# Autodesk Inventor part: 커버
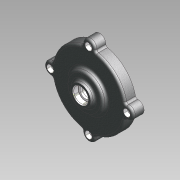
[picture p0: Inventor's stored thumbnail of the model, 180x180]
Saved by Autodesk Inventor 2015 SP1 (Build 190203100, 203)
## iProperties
Company: 한국ATC센터
Created: 2014-07
Part Number: 커버
Document SubType Name: 모델링
Designer: KYOUNG IL JANG
Material: 알루미늄 6061
Mass: 195.931 g
Surface Area: 278.607 cm^2
Volume: 72.5671 cm^3
Density: 2.7 g/cm^3
Appearance: 알루미늄 캐스트
변환 표준: STEP AP214IS
파일 이름: C:\Users\SeoGD\Desktop\?쒗뿕\而ㅻ쾭-1.stp
전처리기: Build: 253, Release: 2010 SP1 - Date: Wed 07/29/2009
전송 단위: 밀리미터
불확실성: 0.01
Author: KYOUNG IL JANG
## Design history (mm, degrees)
sketch "스케치1"
  geometry: L1 (0, 0)-(0, 26); L2 (50, 0)-(50, 15); L3 (50, 15)-(25, 15); L4 (25, 15)-(25, 21); L5 (25, 21)-(15, 21); L6 (15, 21)-(13.66, 26); L7 (13.66, 26)-(10, 26); L8 (50, 0)-(45, 0); L9 (45, 0)-(45, 10); L10 (45, 10)-(14.5, 10); L11 (14.5, 10)-(13.266, 3); L12 (13.266, 3)-(11, 3); L13 (11, 3)-(11, 16); L14 (11, 16)-(7.5, 16); L15 (7.5, 16)-(7.5, 19); L16 (7.5, 19)-(10, 19); L17 (10, 19)-(10, 26)
  constraints: 34 end point, 10 parallel, 2 perpendicular, 2 point on line, 1 vertical
  dimensions: "d11" = 100 diameter of L2 L1; "d12" = 22 diameter of L13 L1; "d13" = 90 diameter of L9 L1; "d14" = 15 distance between parallel lines of L3 L8; "d15" = 10 distance between parallel lines of L8 L10; "d16" = 29 diameter of L10.end L1; "d17" = 100 deg angle of L11 L10; "d18" = 7 distance between parallel lines of L12 L10; "d19" = 13 distance between parallel lines of L14 L12; "d20" = 3 distance between parallel lines of L16 L14; "d21" = 15 diameter of L15 L1; "d22" = 20 diameter of L17 L1; "d23" = 30 diameter of L5.end L1; "d24" = 6 distance between parallel lines of L5 L3; "d25" = 50 diameter of L4 L1; "d26" = 105 deg angle of L5 L6; "d50" = 26 distance of L1.start L1.end
revolve "회전1" sketch "스케치1" stored, may be unused: angle "d27" = 90 deg
sketch "스케치2" dims "d29" = 104
  geometry: A1 r 8.5 centre (0, 52) between (8.074, 49.344) and (-8.074, 49.344); A2 r 50 centre (0, 0) between (-8.074, 49.344) and (8.074, 49.344) reference; 2 further points
  constraints: 4 point on circle, 2 vertical alignment, 1 centre point, 1 coincident, 2 other
  dimensions: "d28" = 17 diameter of A1
extrude "돌출1" join sketch "스케치2" stored distance "d30" = 10; taper "d31" = 0 deg
fillet "모깎기3" dims "d32" = 3
fillet "모깎기4" dims "d45" = 3, "d46" = 0.2
chamfer "모따기1" distance "d47" = 1; stored, may be unused: second distance "d48" = 2, angle "d49" = 45 deg
hole "구멍2" diameter "d38" = 5.5; stored, may be unused: countersink angle "d42" = 90 deg, drill point angle "d44" = 118 deg; dims "d36" = 10, "d37" = 10, "d39" = 6, "d40" = 9.5, "d41" = 5.4, "d43" = 8
node "솔리드1"
node "솔리드 본체"
node "곡면 본체"
pattern_circular "원형 패턴1" dims angle "d34" = 360 deg
pattern_circular "원형 패턴2" dims angle "d52" = 360 deg
node "솔리드2"
